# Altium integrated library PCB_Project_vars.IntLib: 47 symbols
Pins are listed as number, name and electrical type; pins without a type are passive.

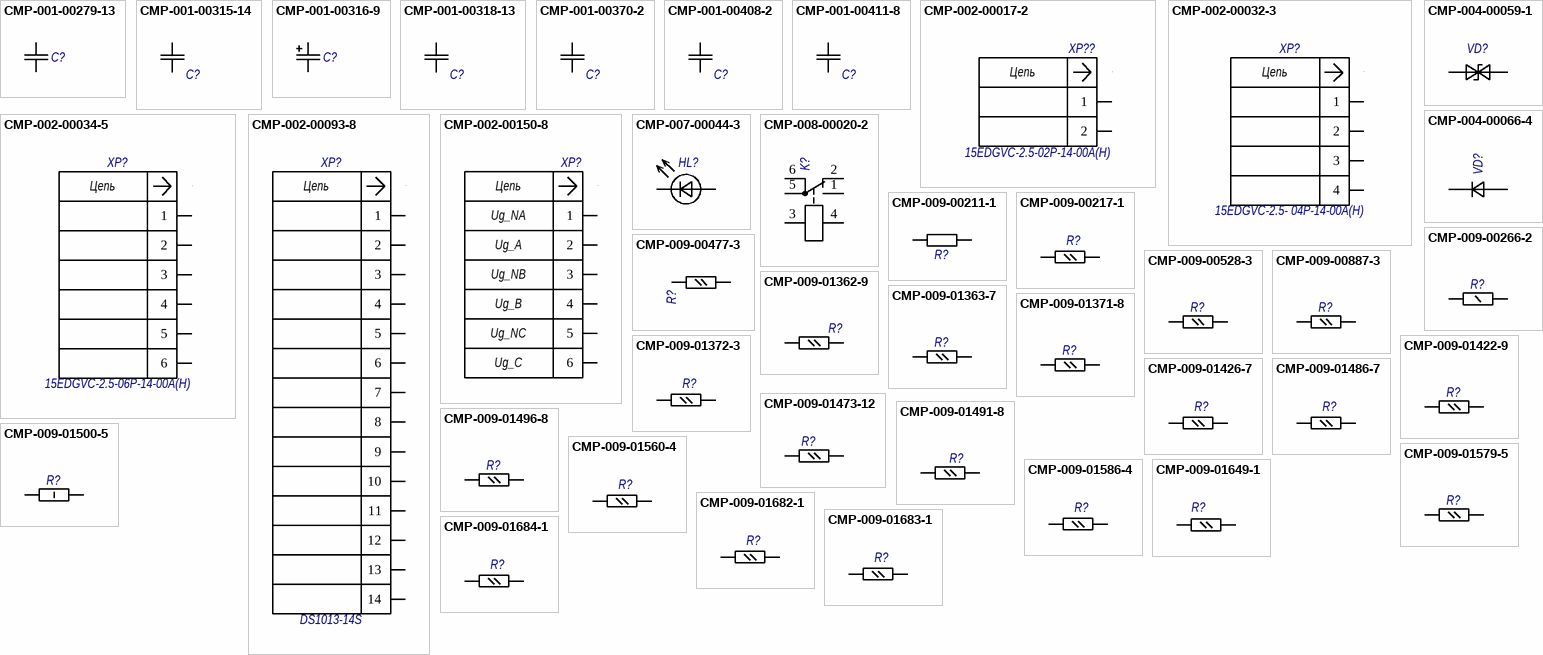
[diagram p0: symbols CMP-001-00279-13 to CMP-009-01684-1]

## CMP-001-00279-13
designator C?, comment GRM21BR71H224K  (value not drawn)
Конденсатор керамический, 220 nF, 50V, ±5%, X7R, 0805; Manufacturer: Murata; Capacitor Type: Ceramic; Value: 220nF
footprint CAPC0805A (Capasitor, Non-polarized, SMD 0805, 2 pins)
footprint CAPC0805B (Capasitor, Non-polarized, SMD 0805, 2 pins)
footprint CAPC0805C (Capasitor, Non-polarized, SMD 0805, 2 pins)
footprint CAPC0805D (Capasitor, Non-polarized, SMD 0805, 2 pins)
pins: 1, 2

## CMP-001-00315-14
designator C?, comment GRM2165C1H221J  (value not drawn)
Конденсатор керамический, 220 pF, 50V, ±5%, 0805; Manufacturer: Murata; Capacitor Type: Ceramic; TKE/TKC: NP0; Value: 220pF; Check: 3
footprint CAPC0805A (Capasitor, Non-polarized, SMD 0805, 2 pins)
footprint CAPC0805B (Capasitor, Non-polarized, SMD 0805, 2 pins)
footprint CAPC0805C (Capasitor, Non-polarized, SMD 0805, 2 pins)
footprint CAPC0805D (Capasitor, Non-polarized, SMD 0805, 2 pins)
pins: 1, 2

## CMP-001-00316-9
designator C?, comment T491B106K016AT  (value not drawn)
Конденсатор танталовый, 10 uF, 16V, ±10%, 3528-21(B); Manufacturer: KEMET; Value: 10µF; Type: Tantal; Ripple Current: 174mA; Dielectric Material: Tantalum; Capacitance: 10uF; Check: 3
footprint C3528-21A (Высокая прочность соединений. Kemet.)
footprint C3528-21B (Соединения общего назначения. Kemet.)
pins: 1, 2

## CMP-001-00318-13
designator C?, comment 08055A102KAT2A  (value not drawn)
Конденсатор керамический, 1 nF, 50V, ±10%, X7R, 0805; Manufacturer: AVX; Capacitor Type: Ceramic; Type: Ceramic capacitor; Value: 1nF
footprint CAPC0805A (Capasitor, Non-polarized, SMD 0805, 2 pins)
footprint CAPC0805B (Capasitor, Non-polarized, SMD 0805, 2 pins)
footprint CAPC0805C (Capasitor, Non-polarized, SMD 0805, 2 pins)
footprint CAPC0805D (Capasitor, Non-polarized, SMD 0805, 2 pins)
pins: 1, 2

## CMP-001-00370-2
designator C?, comment CC0805KKX7R9BB105  (value not drawn)
Конденсатор керамический, 1 uF, 50V, ±10%, X7R, 0805; Manufacturer: Yageo; Capacitor Type: Ceramic; Type: Ceramic capacitor; Value: 1µF; Check: 1
footprint CAPC0805H125A (Capasitor, Non-polarized, SMD 0805, 2 pins)
footprint CAPC0805H125B (Capasitor, Non-polarized, SMD 0805, 2 pins)
footprint CAPC0805H125C (Capasitor, Non-polarized, SMD 0805, 2 pins)
pins: 1, 2

## CMP-001-00408-2
designator C?, comment 0805N103J500CT  (value not drawn)
Конденсатор керамический, 10 nF, 50V, ±5%, NP0, 0805; Manufacturer: Walsin Technologies Corporation; Capacitor Type: Ceramic; Value: 10nF
footprint CAPC0805A (Capasitor, Non-polarized, SMD 0805, 2 pins)
footprint CAPC0805B (Capasitor, Non-polarized, SMD 0805, 2 pins)
footprint CAPC0805C (Capasitor, Non-polarized, SMD 0805, 2 pins)
footprint CAPC0805D (Capasitor, Non-polarized, SMD 0805, 2 pins)
pins: 1, 2

## CMP-001-00411-8
designator C?, comment CC0805KKX7R0BB104  (value not drawn)
Кондесатор керамический,100nF, 100V, 10%, 0805; Manufacturer: Yageo; Capacitor Type: Ceramic; TKE/TKC: X7R; Check: 2
footprint CAPC0805A (Capasitor, Non-polarized, SMD 0805, 2 pins)
footprint CAPC0805B (Capasitor, Non-polarized, SMD 0805, 2 pins)
footprint CAPC0805C (Capasitor, Non-polarized, SMD 0805, 2 pins)
footprint CAPC0805A_(FewerSilk) (Capasitor, Non-polarized, SMD 0805, 2 pins)
footprint CAPC0805B _(FewerSilk) (Capasitor, Non-polarized, SMD 0805, 2 pins)
footprint CAPC0805C_(FewerSilk) (Capasitor, Non-polarized, SMD 0805, 2 pins)
pins: 1, 2

## CMP-002-00017-2
designator XP??, comment 15EDGVC-2.5-02P-14-00A(H)
Клеммник 2-контактный, 4, шаг 2.5 мм, на плату, 2p; Manufacturer: Degson Electronics; Connector Type: Male straight; Gender: Male; Max Current Rating: 4A; Voltage Rating: 150V; Check: 3; Check By: VavilovOA
footprint XP_15EDGVC-2.5-02P (Male straight connector, 2 pins)
pins: 1, 2

## CMP-002-00032-3
designator XP?, comment 15EDGVC-2.5- 04P-14-00A(H)
Клеммник 4-контактный, 4A, шаг 2.5 мм, на плату, 4p; Manufacturer: Degson Electronics; Connector Type: Male straight; Gender: Male; Voltage Rating: 150V; Check: 3; Check By: VavilovOA
footprint XP_15EDGVC-2.5- 04P
pins: 1, 2, 3, 4

## CMP-002-00034-5
designator XP?, comment 15EDGVC-2.5-06P-14-00A(H)
Клеммник 6-контактный, 4A, шаг 2.5 мм, на плату, 6p; Manufacturer: Degson Electronics; Connector Type: Male straight; Gender: Male; Voltage Rating: 150V; Check: 3; Check By: VavilovOA
footprint XP_15EDGVC-2.5- 06P
pins: 1, 2, 3, 4, 5, 6

## CMP-002-00093-8
designator XP?, comment DS1013-14S
Разъем прямой, вилка, 1А, 14p; Manufacturer: Connfly; Connector Type: Male straight; Gender: Male; Max Current Rating: 1A; Voltage Rating: 250V; Check: 2; Check By: VavilovOA
footprint XP_DS1013-14S (Разъем IDC MALE прямой. Разработан по рекомендации производителя Connfly.)
pins: 1, 2, 3, 4, 5, 6, 7, 8, 9, 10, 11, 12, 13, 14

## CMP-002-00150-8
designator XP?, comment 15EDGVC-3.5-06P-14-00AH  (value not drawn)
Разъем прямой, вилка, 8А, 6p; Manufacturer: Электродеталь; Connector Type: Male straight; Gender: Male; Max Current Rating: 8A; Voltage Rating: 400V; VariantName1: Ug_NA; VariantName2: Ug_A; VariantName3: Ug_NB; VariantName4: Ug_B; VariantName5: Ug_NC; VariantName6: Ug_C; Check: 2; Check By: VavilovOA
footprint XP_15EDGVC-3.5
pins: 1, 2, 3, 4, 5, 6

## CMP-004-00059-1
designator VD?, comment SMAJ5.0CA  (value not drawn)
Диод защитный, двусторонний, 5V, DO-214AC, 2p; Manufacturer: STMicroelectronics; ManufacturerPartNumber: SMAJ5.0A(CA); Max Surge Current: 40A; Type: Bidirectional protective diode; Check: 2; Check By: VavilovOA
footprint SMA180P450X230-2 (SMA Package, SMD, Horizontal Mounting, 4.50mm x 2.8mm x 2.30mm, 2 pins)
pins: 1 ANODE, 2 ANODE

## CMP-004-00066-4
designator VD?, comment LL4148  (value not drawn)
Диод, Быстродействующий, 100V, SOD-80, 2p; Manufacturer: Vishay; Check: 3; Forward Current: 300mA; Forward Voltage: 1V; Max Surge Current: 2A; Type: Diode
footprint SOD-80 (miniMELF. Centralsemi.)
pins: 1 CATODE, 2 ANODE

## CMP-007-00044-3
designator HL?, comment 19-217/R6C-AL1M2VY/3T  (value not drawn)
Светодиод красный, 1.7V, 0603, 2p; Manufacturer: Everlight; Colour: RED; Forward Current: 25mA; Max Power Dissipation: 60mW; Type: LED; Check: 3
footprint L0603A (Высокая прочность соединений. ГОСТ IEC 61188-5-2-2013)
pins: 1 CATODE, 2 ANODE

## CMP-008-00020-2
designator K?, comment NRP-03K-C-05D-H  (value not drawn)
Реле электромагнитное, 12.4x7.4x10mm, 6p; Manufacturer: NCR; Contact Form: 1C/O; Current Rating: 1A; Operate Time: 4ms; Check: 2; Check By: VavilovOA
footprint RELAY_NCR_NRP03K (Relay, 12.4x7.4x10mm, 6 pins)
pins: 1, 2, 3, 4, 5, 6

## CMP-009-00211-1
designator R?, comment LTR18EZPFL1R00  (value not drawn)
Резистор постоянный, 0612, 1 W, 1 Ohm ±1%; Manufacturer: Rohm; Power: 1W; Value: 1; Check: 2; Check By: VavilovOA
footprint RESC1632X58_EIA_0612_A (Surface Mount Resistors Chip, 0612, 1.6mm x 3.2mm x 0.58mm, 2 pins)
pins: 1, 2

## CMP-009-00217-1
designator R?, comment RC0805FR-0724K9L  (value not drawn)
Резистор постоянный, 24.9 kOhm, 1%, 0.125W, 0805; Manufacturer: Yageo; Power: 125mW; Value: 24.9k; Voltage Rating: 150V; Check: 3
footprint RESC2012X40_EIA_0805_A (Surface Mount Resistors Chip, 0805, 2mm x 1.3mm x 0.4mm, 2 pins)
footprint RESC2012X40_EIA_0805_B (Surface Mount Resistors Chip, 0805, 2mm x 1.3mm x 0.4mm, 2 pins)
footprint RESC2012X40_EIA_0805_C (Surface Mount Resistors Chip, 0805, 2mm x 1.3mm x 0.4mm, 2 pins)
pins: 1, 2

## CMP-009-00266-2
designator R?, comment CRCW120624K0FKEA  (value not drawn)
Резистор постоянный, 1206, 0.25 W, 24 kOhm ±1%; Manufacturer: VISHAY; Power: 250mW; Value: 24k; Check: 1; Voltage: 200
footprint RESC3216X60_EIA_1206_A (Surface Mount Resistors Chip, 1206, 3.2mm x 1.6mm x 0.6mm, 2 pins)
footprint R1206B (Соединения общего назначения. ГОСТ IEC 61188-5-2-2013)
footprint R1206C (Соединения для плат высокой плотности. ГОСТ IEC 61188-5-2-2013)
pins: 1, 2

## CMP-009-00477-3
designator R?, comment CRCW080533K0FKEA  (value not drawn)
Резистор постоянный, 0805, 0.125 W, 33 kOhm ±1%; Manufacturer: VISHAY; Power: 125mW; Value: 33k; Check: 1; Voltage: 150
footprint RESC2012X40_EIA_0805_A (Surface Mount Resistors Chip, 0805, 2mm x 1.3mm x 0.4mm, 2 pins)
footprint R0805B (Соединения общего назначения. ГОСТ IEC 61188-5-2-2013)
footprint R0805C (Соединения для плат высокой плотности. ГОСТ IEC 61188-5-2-2013)
pins: 1, 2

## CMP-009-00528-3
designator R?, comment CRCW0805620RFKEA  (value not drawn)
Резистор постоянный, 0805, 0.125 W, 620 Ohm ±1%; Manufacturer: VISHAY; Power: 125mW; Value: 620; Check: 1; Voltage: 150
footprint RESC2012X40_EIA_0805_A (Surface Mount Resistors Chip, 0805, 2mm x 1.3mm x 0.4mm, 2 pins)
footprint R0805B (Соединения общего назначения. ГОСТ IEC 61188-5-2-2013)
footprint R0805C (Соединения для плат высокой плотности. ГОСТ IEC 61188-5-2-2013)
pins: 1, 2

## CMP-009-00887-3
designator R?, comment CRCW08051K20FKEA  (value not drawn)
Резистор постоянный, 0805, 0.125 W, 1.2 kOhm ±1%; Manufacturer: VISHAY; Power: 125mW; Value: 1.2k; Check: 1; Voltage: 150
footprint RESC2012X40_EIA_0805_A (Surface Mount Resistors Chip, 0805, 2mm x 1.3mm x 0.4mm, 2 pins)
footprint R0805B (Соединения общего назначения. ГОСТ IEC 61188-5-2-2013)
footprint R0805C (Соединения для плат высокой плотности. ГОСТ IEC 61188-5-2-2013)
pins: 1, 2

## CMP-009-01362-9
designator R?, comment RS-05K104JT  (value not drawn)
Резистор постоянный, 100 kOhm, ±5%, 0.125W, 0805; Manufacturer: Fenghua; Power: 125mW; Value: 100k; Voltage Rating: 150V; Check: 3
footprint RESC2012X40_EIA_0805_A (Surface Mount Resistors Chip, 0805, 2mm x 1.3mm x 0.4mm, 2 pins)
footprint R0805B (Соединения общего назначения. ГОСТ IEC 61188-5-2-2013)
footprint R0805C (Соединения для плат высокой плотности. ГОСТ IEC 61188-5-2-2013)
footprint R0805D (Соединения для плат высокой плотности.)
pins: 1, 2

## CMP-009-01363-7
designator R?, comment RC0805FR-0710KL  (value not drawn)
Резистор постоянный, 10 kOhm, ±1%, 0.125W, 0805; Manufacturer: Yageo; Power: 125mW; Value: 10k; Voltage Rating: 150V; Check: 3
footprint RESC2012X40_EIA_0805_A (Surface Mount Resistors Chip, 0805, 2mm x 1.3mm x 0.4mm, 2 pins)
footprint R0805B (Соединения общего назначения. ГОСТ IEC 61188-5-2-2013)
footprint R0805C (Соединения для плат высокой плотности. ГОСТ IEC 61188-5-2-2013)
footprint R0805D (Соединения для плат высокой плотности.)
pins: 1, 2

## CMP-009-01371-8
designator R?, comment RC0805FR-071KL  (value not drawn)
Резистор постоянный, 1 kOhm, ±1%, 0.125W, 0805; Manufacturer: Yageo; Power: 125mW; Value: 1k; Check: 3; Voltage Rating: 150V
footprint RESC2012X40_EIA_0805_A (Surface Mount Resistors Chip, 0805, 2mm x 1.3mm x 0.4mm, 2 pins)
footprint R0805B (Соединения общего назначения. ГОСТ IEC 61188-5-2-2013)
footprint R0805C (Соединения для плат высокой плотности. ГОСТ IEC 61188-5-2-2013)
footprint R0805D (Соединения для плат высокой плотности.)
pins: 1, 2

## CMP-009-01372-3
designator R?, comment RC0805FR-075K11L  (value not drawn)
5,11 kOhm resistor 1% 0.125W; Manufacturer: Yageo; Power: 125mW; Value: 5.11k; Voltage Rating: 150V
footprint RESC2012X40_EIA_0805_A (Surface Mount Resistors Chip, 0805, 2mm x 1.3mm x 0.4mm, 2 pins)
footprint R0805B (Соединения общего назначения. ГОСТ IEC 61188-5-2-2013)
footprint R0805C (Соединения для плат высокой плотности. ГОСТ IEC 61188-5-2-2013)
pins: 1, 2

## CMP-009-01422-9
designator R?, comment RI0805L103JT  (value not drawn)
Резистор постоянный, 10 kOhm, ±5%, 0.125W, 0805; Manufacturer: Hottech; Power: 125mW; Value: 10k; Voltage Rating: 150V; Check: 3
footprint RESC2012X40_EIA_0805_A (Surface Mount Resistors Chip, 0805, 2mm x 1.3mm x 0.4mm, 2 pins)
footprint RESC2012X40_EIA_0805_B (Surface Mount Resistors Chip, 0805, 2mm x 1.3mm x 0.4mm, 2 pins)
footprint RESC2012X40_EIA_0805_C (Surface Mount Resistors Chip, 0805, 2mm x 1.3mm x 0.4mm, 2 pins)
footprint R0805D (Соединения для плат высокой плотности.)
pins: 1, 2

## CMP-009-01426-7
designator R?, comment RI0805L3301FT  (value not drawn)
Резистор постоянный, 3.3 kOhm, ±1%, 0.125W, 0805; Manufacturer: HOTTECH; Power: 125mW; Value: 3.3k; Voltage Rating: 150V; Check: 3
footprint RESC2012X40_EIA_0805_A (Surface Mount Resistors Chip, 0805, 2mm x 1.3mm x 0.4mm, 2 pins)
footprint R0805B (Соединения общего назначения. ГОСТ IEC 61188-5-2-2013)
footprint R0805C (Соединения для плат высокой плотности. ГОСТ IEC 61188-5-2-2013)
footprint R0805D (Соединения для плат высокой плотности.)
pins: 1, 2

## CMP-009-01473-12
designator R?, comment CRCW0805100RJNEA  (value not drawn)
Резистор постоянный, 100 Ohm, ±5%, 0.125W, 0805; Manufacturer: VISHAY INTERTECHNOLOGY INC.; Power: 125mW; Value: 100; Voltage Rating: 150V; Check: 3
footprint RESC2012X40_EIA_0805_A (Surface Mount Resistors Chip, 0805, 2mm x 1.3mm x 0.4mm, 2 pins)
footprint RESC2012X40_EIA_0805_B (Surface Mount Resistors Chip, 0805, 2mm x 1.3mm x 0.4mm, 2 pins)
footprint RESC2012X40_EIA_0805_C (Surface Mount Resistors Chip, 0805, 2mm x 1.3mm x 0.4mm, 2 pins)
footprint RESC2012X40_EIA_0805_A_(FewerSilk) (Surface Mount Resistors Chip, 0805, 2mm x 1.3mm x 0.4mm, 2 pins)
footprint RESC2012X40_EIA_0805_B_(FewerSilk) (Surface Mount Resistors Chip, 0805, 2mm x 1.3mm x 0.4mm, 2 pins)
footprint RESC2012X40_EIA_0805_C_(FewerSilk) (Surface Mount Resistors Chip, 0805, 2mm x 1.3mm x 0.4mm, 2 pins)
pins: 1, 2

## CMP-009-01486-7
designator R?, comment RC0805FR-072KL  (value not drawn)
Резистор постоянный, 2 kOhm, ±1%, 0.125W, 0805; Manufacturer: YAGEO; Power: 125mW; Value: 2k; Voltage Rating: 150V; Temperature Coefficient: 100ppm/°C
footprint RESC2012X40_EIA_0805_A (Surface Mount Resistors Chip, 0805, 2mm x 1.3mm x 0.4mm, 2 pins)
footprint R0805B (Соединения общего назначения. ГОСТ IEC 61188-5-2-2013)
footprint R0805C (Соединения для плат высокой плотности. ГОСТ IEC 61188-5-2-2013)
footprint R0805D (Соединения для плат высокой плотности.)
pins: 1, 2

## CMP-009-01491-8
designator R?, comment RC0805FR-071K3L  (value not drawn)
Резистор постоянный, 1.3 kOhm, ±1%, 0.125W, 0805; Manufacturer: YAGEO; Power: 125mW; Value: 1.3k; Voltage Rating: 150V; Temperature Coefficient: 100ppm/°C; Check: 3
footprint RESC2012X40_EIA_0805_A (Surface Mount Resistors Chip, 0805, 2mm x 1.3mm x 0.4mm, 2 pins)
footprint R0805B (Соединения общего назначения. ГОСТ IEC 61188-5-2-2013)
footprint R0805C (Соединения для плат высокой плотности. ГОСТ IEC 61188-5-2-2013)
footprint R0805D (Соединения для плат высокой плотности.)
pins: 1, 2

## CMP-009-01496-8
designator R?, comment RC0805FR-07330RL  (value not drawn)
Резистор постоянный, 330 Ohm, ±1%, 0.125W, 0805; Manufacturer: Yageo; Power: 125mW; Value: 330; Voltage Rating: 150V; Check: 3
footprint RESC2012X40_EIA_0805_A (Surface Mount Resistors Chip, 0805, 2mm x 1.3mm x 0.4mm, 2 pins)
footprint R0805B (Соединения общего назначения. ГОСТ IEC 61188-5-2-2013)
footprint R0805C (Соединения для плат высокой плотности. ГОСТ IEC 61188-5-2-2013)
footprint R0805D (Соединения для плат высокой плотности.)
pins: 1, 2

## CMP-009-01500-5
designator R?, comment RC2512FR-07300KL  (value not drawn)
Резистор постоянный, 300 kOhm, ±1%, 1W, 2512; Manufacturer: THUNDER; ManufacturerPartNumber: RC2512; Value: 300k; Voltage Rating: 200V; Check: 3
footprint RESC6332X60_EIA_2512_A (Surface Mount Resistors Chip, 2512, 6.3mm x 3.2mm x 0.6mm, 2 pins)
footprint R2512B (Соединения общего назначения. ГОСТ IEC 61188-5-2-2013)
pins: 1, 2

## CMP-009-01560-4
designator R?, comment KSE-0805FR-074K7L  (value not drawn)
Резистор постоянный, 4.7 kOhm, ±1%, 0.125W, 0805; Manufacturer: KEEN SIDE; Check: 3; Power: 125mW; Value: 4.7k; Voltage Rating: 150V
footprint RESC2012X40_EIA_0805_A (Surface Mount Resistors Chip, 0805, 2mm x 1.3mm x 0.4mm, 2 pins)
footprint R0805B (Соединения общего назначения. ГОСТ IEC 61188-5-2-2013)
footprint R0805C (Соединения для плат высокой плотности. ГОСТ IEC 61188-5-2-2013)
footprint R0805D (Соединения для плат высокой плотности.)
pins: 1, 2

## CMP-009-01579-5
designator R?, comment RC0805JR-071K6L  (value not drawn)
Резистор постоянный, 1.6 kOhm, ±5%, 0.125W, 0805; Manufacturer: Yageo; Power: 125mW; Value: 1.6k; Voltage Rating: 150V; Check: 3
footprint RESC2012X40_EIA_0805_A (Surface Mount Resistors Chip, 0805, 2mm x 1.3mm x 0.4mm, 2 pins)
footprint R0805B (Соединения общего назначения. ГОСТ IEC 61188-5-2-2013)
footprint R0805C (Соединения для плат высокой плотности. ГОСТ IEC 61188-5-2-2013)
footprint R0805D (Соединения для плат высокой плотности.)
pins: 1, 2

## CMP-009-01586-4
designator R?, comment RI0805L203JT  (value not drawn)
Резистор постоянный, 20 kOhm, ±5%, 0.125W, 0805; Manufacturer: Hottech; Power: 125mW; Value: 20k; Voltage Rating: 150V; Check: 3
footprint RESC2012X40_EIA_0805_A (Surface Mount Resistors Chip, 0805, 2mm x 1.3mm x 0.4mm, 2 pins)
footprint R0805B (Соединения общего назначения. ГОСТ IEC 61188-5-2-2013)
footprint R0805C (Соединения для плат высокой плотности. ГОСТ IEC 61188-5-2-2013)
footprint R0805D (Соединения для плат высокой плотности.)
pins: 1, 2

## CMP-009-01649-1
designator R?, comment CRCW0805560RFKEA  (value not drawn)
Резистор постоянный, 0805, 0.125 W, 560 Ohm ±1%; Manufacturer: VISHAY; Power: 125mW; Value: 560; Check: 2; Voltage Rating: 150V
footprint RESC2012X40_EIA_0805_A (Surface Mount Resistors Chip, 0805, 2mm x 1.3mm x 0.4mm, 2 pins)
footprint RESC2012X40_EIA_0805_B (Surface Mount Resistors Chip, 0805, 2mm x 1.3mm x 0.4mm, 2 pins)
footprint RESC2012X40_EIA_0805_C (Surface Mount Resistors Chip, 0805, 2mm x 1.3mm x 0.4mm, 2 pins)
pins: 1, 2

## CMP-009-01682-1
designator R?, comment RC0805FR-072K8L  (value not drawn)
Резистор постоянный, 2.8 kOhm, ±1%, 0.125W, 0805; Manufacturer: YAGEO; Power: 125mW; Value: 2.8k; Voltage Rating: 150V; Temperature Coefficient: 100ppm/°C; Check: 2
footprint RESC2012X40_EIA_0805_A (Surface Mount Resistors Chip, 0805, 2mm x 1.3mm x 0.4mm, 2 pins)
footprint RESC2012X40_EIA_0805_B (Surface Mount Resistors Chip, 0805, 2mm x 1.3mm x 0.4mm, 2 pins)
footprint RESC2012X40_EIA_0805_C (Surface Mount Resistors Chip, 0805, 2mm x 1.3mm x 0.4mm, 2 pins)
footprint R0805D (Соединения для плат высокой плотности.)
pins: 1, 2

## CMP-009-01683-1
designator R?, comment RC0805FR-073KL  (value not drawn)
Резистор постоянный, 3 kOhm, 1%, 0.125W, 0805; Manufacturer: Yageo; Power: 125mW; Value: 3k; Voltage Rating: 150V; Check: 3
footprint RESC2012X40_EIA_0805_A (Surface Mount Resistors Chip, 0805, 2mm x 1.3mm x 0.4mm, 2 pins)
footprint RESC2012X40_EIA_0805_B (Surface Mount Resistors Chip, 0805, 2mm x 1.3mm x 0.4mm, 2 pins)
footprint RESC2012X40_EIA_0805_C (Surface Mount Resistors Chip, 0805, 2mm x 1.3mm x 0.4mm, 2 pins)
pins: 1, 2

## CMP-009-01684-1
designator R?, comment RC0805FR-0715K4L  (value not drawn)
Резистор постоянный, 15.4 kOhm, 1%, 0,125W, 0805; Manufacturer: Yageo; Power: 125mW; Value: 15.4k; Voltage Rating: 150V; Check: 2
footprint RESC2012X40_EIA_0805_A (Surface Mount Resistors Chip, 0805, 2mm x 1.3mm x 0.4mm, 2 pins)
footprint RESC2012X40_EIA_0805_B (Surface Mount Resistors Chip, 0805, 2mm x 1.3mm x 0.4mm, 2 pins)
footprint RESC2012X40_EIA_0805_C (Surface Mount Resistors Chip, 0805, 2mm x 1.3mm x 0.4mm, 2 pins)
pins: 1, 2

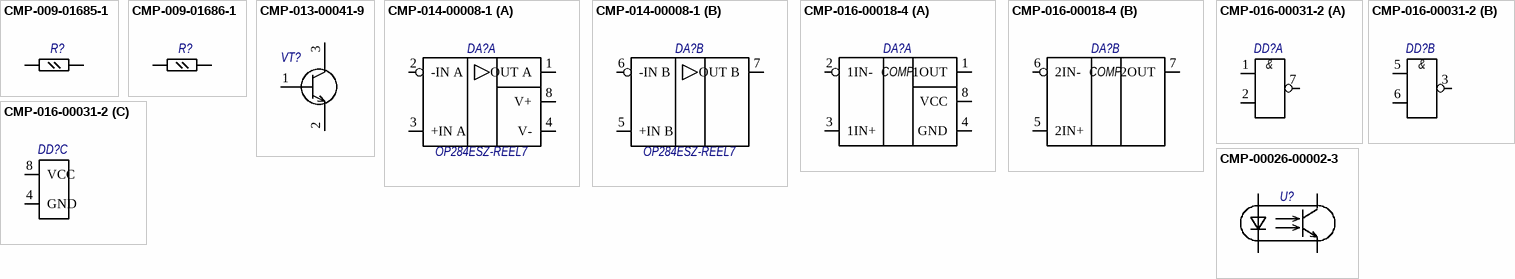
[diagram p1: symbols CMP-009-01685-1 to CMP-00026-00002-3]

## CMP-009-01685-1
designator R?, comment RC0805FR-074K3L  (value not drawn)
Резистор постоянный, 4.3 kOhm, 1%, 0,125W, 0805; Manufacturer: Yageo; Power: 125mW; Value: 4.3k; Voltage Rating: 150V; Check: 2; Check By: VavilovOA
footprint RESC2012X40_EIA_0805_A (Surface Mount Resistors Chip, 0805, 2mm x 1.3mm x 0.4mm, 2 pins)
footprint RESC2012X40_EIA_0805_B (Surface Mount Resistors Chip, 0805, 2mm x 1.3mm x 0.4mm, 2 pins)
footprint RESC2012X40_EIA_0805_C (Surface Mount Resistors Chip, 0805, 2mm x 1.3mm x 0.4mm, 2 pins)
pins: 1, 2

## CMP-009-01686-1
designator R?, comment RC0805FR-076K2L  (value not drawn)
Резистор постоянный, 6.2 kOhm, ±1%, 0.125W, 0805; Manufacturer: Yageo; Power: 125mW; Value: 6.2k; Voltage Rating: 150V; Check: 3
footprint RESC2012X40_EIA_0805_A (Surface Mount Resistors Chip, 0805, 2mm x 1.3mm x 0.4mm, 2 pins)
footprint RESC2012X40_EIA_0805_B (Surface Mount Resistors Chip, 0805, 2mm x 1.3mm x 0.4mm, 2 pins)
footprint R0805C (Соединения для плат высокой плотности. ГОСТ IEC 61188-5-2-2013)
footprint R0805D (Соединения для плат высокой плотности.)
pins: 1, 2

## CMP-013-00041-9
designator VT?, comment 2SC3265  (value not drawn)
Транзистор BJT-NPN, 0.8А, 30V, SOT-23-3, 3p; Manufacturer: UMW; ManufacturerPartNumber: UMW 2SC3265; Type: TRANSISTOR (NPN); Collector-Base Voltage: 35; Collector-Emitter Voltage: 30; Frequency: 120MHz; Power: 200mW; Transistor Type: NPN; Emitter-Base Voltage: 5; Collector Current -Continuous: 0.8; Check: 3
footprint SOT210P264X112-3_1V1 (SOT23 Package, SMD, Horizontal Mounting, 2.8mm x 1.2mm x 1.12mm, 2 pins, Pitch 0.95mm)
pins: 1 BASE, 2 EMITTER, 3 COLLECTOR

## CMP-014-00008-1
designator DA?, comment OP284ESZ-REEL7
Операционный усилитель, сдвоенный, SOIC-8, 8p; Manufacturer: Analog Devices; Channels: 2; Max Supply Voltage: 18V; Min Supply Voltage: -18V; Nominal Gain Bandwidth Product: 4.25MHz; Output Type: Operational Amplifier; Раздел: Amplifier; Check: 3
footprint SOIC127P620X175-8 (Small Outline Integrated Circuit, 5.0mm x 4.0mm x 1.75mm, Pitch 1.27mm, 8 pins)
part A pins: 1 OUT A, 2 -IN A, 3 +IN A, 4 V-, 8 V+
part B pins: 5 +IN B, 6 -IN B, 7 OUT B

## CMP-016-00018-4
designator DA?, comment LM193DR  (value not drawn)
Компаратор, двойной, SOP-8, 8p; Manufacturer: TEXAS; Frequency: 0Hz; Logic Type: Comparator; Max Power Dissipation: 570mW; Max Supply Voltage: 32V; Min Supply Voltage: 2V; Nominal Supply Current: 2.5mA; Nominal Supply Voltage: 15V
footprint SO-8_8P (JEDEC MS-012. IPC-SM-782A.)
part A pins: 1 1OUT, 2 1IN-, 3 1IN+, 4 GND, 8 VCC
part B pins: 5 2IN+, 6 2IN-, 7 2OUT

## CMP-016-00031-2
designator DD?, comment SN74LVC2G00DCTR  (value not drawn)
2И-НЕ, x2, 4 входа, CMOS, SM8, 8p; Manufacturer: Texas Instruments; Check: 2; Check By: VavilovOA; Logic Type: 2-Input NAND; Max Supply Voltage: 6.5V; Min Supply Voltage: -500mV; Output Function: NAND
footprint SOP65P400X130-8 (SM-8, SSOP-8, DCT, 2.9 x 3.15 x 1.3mm, pitch 0.65mm, 8 pins)
part A pins: 1 1A, 2 1B, 7 1Y
part B pins: 3 2Y, 5 2A, 6 2B
part C pins: 4 GND, 8 VCC

## CMP-00026-00002-3
designator U?, comment PB181S  (value not drawn)
Оптопара транзисторная, SOP-4, 4p; Manufacturer: ОАО "Протон"; TU/GOST: КЕНС 431156.091 ТУ; Check: 3
footprint SOP-4 (TAIWAN SEMICONDUCTOR)
pins: 1 A1, 2 C1, 3 A2, 4 C2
